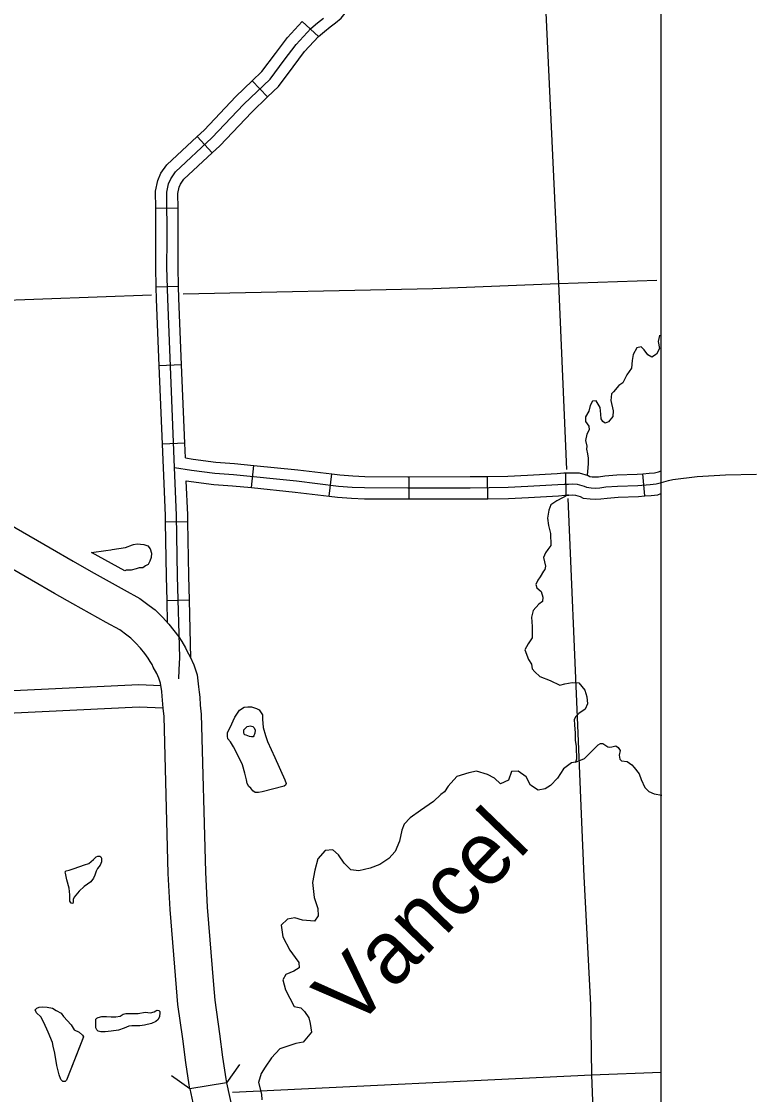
# Model space of a CAD drawing. Extents: x -5566 to 1759129, y -3726 to 731467.
# Drawn here: x -4479.3 to -4442.1, y 243.7 to 298.6 of the extents above; entities that cross this region are included whole.
import ezdxf

# ---------------------------------------------------------------- set-up
doc = ezdxf.new("R2010")
doc.units = 0
doc.layers.add('Default', color=7, linetype='Continuous')
doc.layers.add('R_No Plot', color=7, linetype='Continuous')

msp = doc.modelspace()

# ---------------------------------------------------------------- linework, layer by layer
at = {"layer": 'Default'}
for p, q in [((-4464.085, 297.804), (-4464.921, 298.578)), ((-4466.687, 294.72), (-4467.474, 295.544)), ((-4469.51, 291.865), (-4470.287, 292.698)), ((-4471.258, 289.031), (-4472.397, 289.024)), ((-4471.229, 285.033), (-4472.368, 285.003)), ((-4471.077, 281.034), (-4472.215, 280.989)), ((-4470.916, 277.028), (-4472.054, 276.982)), ((-4467.512, 274.759), (-4467.397, 275.893)), ((-4463.537, 274.323), (-4463.401, 275.454)), ((-4459.465, 274.177), (-4459.465, 275.316)), ((-4455.446, 274.193), (-4455.465, 275.332)), ((-4451.448, 274.371), (-4451.453, 275.51)), ((-4447.431, 274.33), (-4447.528, 275.464)), ((-4470.759, 273.008), (-4471.898, 272.989)), ((-4470.681, 269.005), (-4471.82, 268.974))]:
    msp.add_line(p, q, dxfattribs=at)
for points in [[(-4453.482, 320.514), (-4451.836, 285.18)], [(-4464.085, 297.804), (-4464.083, 297.806), (-4463.78, 298.068), (-4463.49, 298.302), (-4463.213, 298.502), (-4462.932, 298.744), (-4462.543, 299.237), (-4462.261, 299.644), (-4461.9, 300.068), (-4461.596, 300.614), (-4461.455, 301.062)], [(-4471.219, 264.982), (-4471.203, 265.443), (-4471.172, 266.072), (-4471.284, 270.231), (-4471.334, 273.342), (-4471.436, 275.786), (-4471.783, 284.412), (-4471.826, 286.024), (-4471.817, 287.421), (-4471.833, 289.851), (-4471.74, 290.286), (-4471.628, 290.543), (-4471.397, 290.886), (-4469.528, 292.627), (-4467.9, 294.35), (-4466.554, 295.635), (-4465.834, 296.596), (-4465.234, 297.402), (-4464.479, 298.217), (-4464.145, 298.505), (-4463.836, 298.754)], [(-4467.474, 295.544), (-4466.981, 296.015), (-4466.29, 296.937), (-4465.672, 297.767), (-4464.921, 298.578)], [(-4466.687, 294.72), (-4466.126, 295.256), (-4465.377, 296.255), (-4464.795, 297.037), (-4464.085, 297.804)], [(-4470.287, 292.698), (-4469.93, 293.031), (-4468.303, 294.752), (-4467.474, 295.544)], [(-4469.51, 291.865), (-4469.127, 292.222), (-4467.496, 293.948), (-4466.687, 294.72)], [(-4472.397, 289.024), (-4472.403, 289.909), (-4472.285, 290.46), (-4472.13, 290.818), (-4471.833, 291.258), (-4470.287, 292.698)], [(-4471.258, 289.031), (-4471.263, 289.792), (-4471.195, 290.111), (-4471.127, 290.268), (-4470.961, 290.513), (-4469.51, 291.865)], [(-4472.368, 285.003), (-4472.395, 286.018), (-4472.387, 287.421), (-4472.397, 289.024)], [(-4471.229, 285.033), (-4471.256, 286.03), (-4471.247, 287.422), (-4471.258, 289.031)], [(-4470.996, 284.653), (-4458.259, 284.927), (-4451.836, 285.18), (-4446.814, 285.36)], [(-4451.836, 285.18), (-4451.428, 275.683)], [(-4496.493, 283.663), (-4492.047, 283.887), (-4472.622, 284.605)], [(-4472.215, 280.989), (-4472.352, 284.393), (-4472.368, 285.003)], [(-4471.077, 281.034), (-4471.213, 284.431), (-4471.229, 285.033)], [(-4446.675, 282.548), (-4446.674, 282.535), (-4446.755, 282.226)], [(-4446.755, 282.226), (-4446.683, 281.864), (-4446.831, 281.582), (-4447.067, 281.419), (-4447.275, 281.538), (-4447.467, 281.804), (-4447.615, 281.952), (-4447.837, 281.893), (-4448.029, 281.567), (-4448.074, 281.257), (-4448.103, 280.858), (-4448.346, 280.526), (-4448.544, 280.115), (-4448.76, 279.968), (-4449.022, 279.661), (-4449.125, 279.555), (-4449.165, 279.214), (-4449.036, 278.681), (-4449.066, 278.4), (-4449.288, 278.118), (-4449.45, 278.059), (-4449.569, 278.133), (-4449.658, 278.266), (-4449.672, 278.518), (-4449.702, 278.844), (-4449.909, 279.199), (-4450.102, 279.17), (-4450.22, 278.962), (-4450.294, 278.666), (-4450.457, 278.37), (-4450.457, 278.133), (-4450.279, 277.896), (-4450.275, 277.707), (-4450.391, 277.488), (-4450.462, 277.174), (-4450.383, 276.875), (-4450.407, 276.716), (-4450.362, 276.476), (-4450.317, 276.255), (-4450.317, 275.992), (-4450.341, 275.772), (-4450.378, 275.388)], [(-4472.054, 276.982), (-4472.215, 280.989)], [(-4470.916, 277.028), (-4471.077, 281.034)], [(-4494.144, 278.929), (-4493.211, 280.583), (-4483.34, 274.875), (-4477.782, 271.676), (-4476.612, 270.994), (-4475.698, 270.468), (-4474.009, 269.528), (-4473.203, 269.087), (-4472.738, 268.742), (-4472.428, 268.505), (-4472.055, 268.145), (-4471.737, 267.781), (-4471.471, 267.459), (-4471.225, 267.131), (-4471.068, 266.89), (-4470.879, 266.579), (-4470.815, 266.422), (-4470.638, 266.114), (-4470.459, 265.699)], [(-4472.233, 265.028), (-4472.339, 265.263), (-4472.526, 265.588), (-4472.581, 265.723), (-4472.675, 265.879), (-4472.782, 266.043), (-4472.962, 266.284), (-4473.183, 266.55), (-4473.432, 266.835), (-4473.668, 267.063), (-4473.88, 267.225), (-4474.23, 267.485), (-4474.926, 267.866), (-4476.633, 268.816), (-4477.564, 269.351), (-4478.734, 270.033), (-4484.29, 273.232), (-4494.144, 278.929)], [(-4471.898, 272.989), (-4471.904, 273.326), (-4472.005, 275.763), (-4472.054, 276.982)], [(-4470.885, 276.273), (-4470.916, 277.028)], [(-4470.885, 276.273), (-4470.491, 276.208), (-4469.322, 276.056), (-4468.376, 275.992), (-4467.397, 275.893)], [(-4467.397, 275.893), (-4465.145, 275.664), (-4463.401, 275.454)], [(-4471.436, 275.786), (-4470.574, 275.644), (-4469.377, 275.489), (-4468.424, 275.424), (-4465.208, 275.098), (-4463.061, 274.84), (-4462.371, 274.789), (-4461.732, 274.759), (-4459.532, 274.747), (-4456.338, 274.748), (-4454.409, 274.779), (-4453.395, 274.824), (-4451.871, 274.913), (-4451.541, 274.94), (-4451.319, 274.941), (-4451.098, 274.952), (-4450.879, 274.942), (-4450.531, 274.839), (-4450.407, 274.779), (-4450.163, 274.745), (-4449.954, 274.735), (-4449.732, 274.75), (-4449.417, 274.791), (-4448.825, 274.84), (-4447.791, 274.87), (-4447.159, 274.925), (-4446.848, 274.951), (-4446.584, 275.012), (-4446.22, 275.114), (-4446.003, 275.173), (-4444.758, 275.327), (-4443.31, 275.408), (-4441.732, 275.442)], [(-4463.401, 275.454), (-4463.006, 275.407), (-4462.337, 275.358), (-4461.717, 275.328), (-4459.531, 275.316), (-4459.465, 275.316)], [(-4459.465, 275.316), (-4456.343, 275.318), (-4455.465, 275.332)], [(-4455.465, 275.332), (-4454.426, 275.349), (-4453.424, 275.393), (-4451.911, 275.481), (-4451.566, 275.51), (-4451.453, 275.51)], [(-4451.453, 275.51), (-4451.334, 275.511), (-4451.099, 275.522), (-4450.784, 275.508), (-4450.324, 275.372), (-4450.239, 275.331), (-4450.11, 275.313), (-4449.959, 275.305), (-4449.788, 275.317), (-4449.477, 275.357), (-4448.857, 275.409), (-4447.823, 275.439), (-4447.528, 275.464)], [(-4447.528, 275.464), (-4447.208, 275.492), (-4446.936, 275.515), (-4446.725, 275.564), (-4446.6, 275.609), (-4446.6, 275.609), (-4446.6, 275.609), (-4446.6, 275.609)], [(-4470.759, 273.008), (-4470.765, 273.359), (-4470.837, 275.104)], [(-4470.837, 275.104), (-4469.433, 274.922), (-4468.471, 274.857), (-4467.512, 274.759)], [(-4467.512, 274.759), (-4465.271, 274.532), (-4463.537, 274.323)], [(-4463.537, 274.323), (-4463.116, 274.273), (-4462.406, 274.22), (-4461.747, 274.189), (-4459.533, 274.177), (-4459.465, 274.177)], [(-4459.465, 274.177), (-4456.333, 274.179), (-4455.446, 274.193)], [(-4455.446, 274.193), (-4454.392, 274.21), (-4453.366, 274.255), (-4451.83, 274.344), (-4451.516, 274.371), (-4451.448, 274.371)], [(-4451.341, 274.393), (-4451.919, 274.084), (-4452.226, 273.876), (-4452.335, 273.613), (-4452.401, 273.197), (-4452.346, 272.824), (-4452.237, 272.419)], [(-4451.448, 274.371), (-4451.304, 274.372), (-4451.096, 274.382), (-4450.974, 274.376), (-4450.737, 274.306), (-4450.574, 274.227), (-4450.216, 274.178), (-4449.949, 274.164), (-4449.676, 274.183), (-4449.356, 274.224), (-4448.793, 274.271), (-4447.758, 274.301), (-4447.431, 274.33)], [(-4451.365, 274.195), (-4450.868, 262.62), (-4450.669, 257.665), (-4450.539, 254.888), (-4450.203, 248.323), (-4450.151, 244.733)], [(-4447.431, 274.33), (-4447.111, 274.357), (-4446.759, 274.387), (-4446.614, 274.46), (-4446.614, 274.46), (-4446.614, 274.46), (-4446.614, 274.46), (-4446.614, 274.46)], [(-4471.82, 268.974), (-4471.853, 270.218), (-4471.898, 272.989)], [(-4470.681, 269.005), (-4470.714, 270.243), (-4470.759, 273.008)], [(-4452.237, 272.419), (-4452.226, 271.805), (-4452.379, 271.597), (-4452.5, 271.433), (-4452.601, 271.194), (-4452.5, 270.743), (-4452.533, 270.567), (-4452.606, 270.492), (-4452.763, 270.206), (-4452.883, 270.031), (-4452.993, 269.811), (-4452.949, 269.636), (-4452.719, 269.45), (-4452.642, 269.154), (-4452.653, 268.946), (-4452.84, 268.8), (-4453.125, 268.484), (-4453.219, 268.146), (-4453.186, 267.667), (-4453.188, 267.087)], [(-4473.404, 270.615), (-4473.653, 270.542), (-4473.901, 270.542), (-4473.971, 270.512), (-4475.676, 271.441), (-4474.952, 271.545), (-4474.694, 271.578), (-4474.623, 271.599)], [(-4474.623, 271.599), (-4473.944, 271.698), (-4473.59, 271.838), (-4473.527, 271.856), (-4473.348, 271.879), (-4473.005, 271.849), (-4472.801, 271.783), (-4472.68, 271.634), (-4472.616, 271.408), (-4472.629, 271.191), (-4472.695, 270.994), (-4472.792, 270.822), (-4472.925, 270.762), (-4473.064, 270.658), (-4473.246, 270.658), (-4473.404, 270.615)], [(-4471.789, 267.844), (-4471.82, 268.974)], [(-4470.602, 266.051), (-4470.681, 269.005)], [(-4453.188, 267.087), (-4453.389, 266.768), (-4453.552, 266.465)], [(-4453.552, 266.465), (-4453.362, 265.97), (-4453.219, 265.734), (-4453.184, 265.492), (-4453.047, 265.343), (-4452.789, 265.113), (-4452.253, 264.897), (-4451.773, 264.663), (-4451.518, 264.73), (-4451.142, 264.802), (-4450.791, 264.782), (-4450.489, 264.401), (-4450.381, 264.071), (-4450.347, 263.715), (-4450.469, 263.434), (-4450.8, 263.218), (-4450.952, 263.066), (-4451.038, 262.905), (-4451.02, 262.635), (-4450.981, 262.203), (-4450.986, 261.852), (-4450.932, 261.526), (-4450.927, 261.29), (-4450.909, 261.092), (-4450.921, 260.878), (-4450.959, 260.724), (-4451.172, 260.701)], [(-4470.459, 265.699), (-4470.289, 265.19), (-4470.213, 264.581), (-4470.175, 264.31), (-4470.152, 264.048), (-4470.125, 263.643), (-4470.079, 263.187), (-4469.86, 255.114), (-4469.768, 253.326), (-4469.454, 249.352), (-4469.386, 248.563), (-4469.14, 246.84), (-4468.987, 245.647), (-4468.819, 244.545), (-4468.786, 244.346), (-4470.659, 244.032)], [(-4470.659, 244.032), (-4470.694, 244.245), (-4470.867, 245.383), (-4471.022, 246.585), (-4471.273, 248.348), (-4471.346, 249.196), (-4471.663, 253.202), (-4471.758, 255.04), (-4471.975, 263.067), (-4472.017, 263.486), (-4472.045, 263.901), (-4472.062, 264.095), (-4472.095, 264.332), (-4472.15, 264.773), (-4472.233, 265.028)], [(-4472.133, 264.637), (-4473.255, 264.672), (-4481.447, 264.286), (-4482.582, 264.244), (-4483.267, 264.115), (-4483.816, 264.024), (-4484.6, 264.043), (-4485.108, 264.043), (-4486.112, 264.063), (-4486.717, 264.042), (-4490.419, 263.887), (-4490.372, 262.749)], [(-4472.018, 263.493), (-4473.246, 263.532), (-4481.399, 263.148), (-4482.455, 263.109), (-4483.068, 262.994), (-4483.735, 262.882), (-4484.614, 262.904), (-4485.12, 262.904), (-4486.104, 262.924), (-4486.674, 262.904), (-4490.372, 262.749)], [(-4467.975, 260.595), (-4468.188, 261.052), (-4468.421, 261.508), (-4468.573, 261.762), (-4468.715, 261.924), (-4468.736, 262.056), (-4468.736, 262.249), (-4468.604, 262.492), (-4468.361, 263.02), (-4468.117, 263.385), (-4467.884, 263.537), (-4467.691, 263.557), (-4467.509, 263.557), (-4467.255, 263.466), (-4467.113, 263.395), (-4466.941, 263.141), (-4466.941, 262.918), (-4466.911, 262.492), (-4466.789, 262.086), (-4466.688, 261.782)], [(-4467.61, 262.041), (-4467.783, 262.112), (-4467.849, 262.132), (-4467.884, 262.162), (-4467.899, 262.239), (-4467.899, 262.315), (-4467.894, 262.381), (-4467.828, 262.452), (-4467.783, 262.507), (-4467.727, 262.558), (-4467.651, 262.573)], [(-4467.651, 262.573), (-4467.57, 262.583), (-4467.448, 262.543), (-4467.372, 262.482), (-4467.316, 262.37), (-4467.346, 262.208), (-4467.386, 262.066), (-4467.418, 262.026), (-4467.509, 262.026), (-4467.61, 262.041)], [(-4466.688, 261.782), (-4466.312, 260.96), (-4465.805, 259.824), (-4465.745, 259.632), (-4465.775, 259.551), (-4465.846, 259.51), (-4466.961, 259.216), (-4467.154, 259.175), (-4467.326, 259.185), (-4467.438, 259.267), (-4467.549, 259.398), (-4467.651, 259.49), (-4467.732, 259.632), (-4467.772, 259.824), (-4467.843, 260.169), (-4467.975, 260.595)], [(-4450.959, 260.724), (-4450.505, 260.923), (-4449.941, 261.47), (-4449.804, 261.622), (-4449.686, 261.682), (-4449.571, 261.68), (-4449.422, 261.588), (-4449.312, 261.518), (-4449.22, 261.5), (-4449.114, 261.52), (-4448.904, 261.569), (-4448.785, 261.484), (-4448.693, 261.321), (-4448.742, 261.09), (-4448.701, 260.878), (-4448.62, 260.791), (-4448.337, 260.767), (-4448.085, 260.597), (-4447.964, 260.458), (-4447.711, 260.128), (-4447.612, 259.843), (-4447.431, 259.426), (-4447.215, 259.238), (-4446.958, 259.107), (-4446.562, 259.039)], [(-4451.172, 260.701), (-4451.573, 260.383), (-4451.882, 259.914), (-4452.236, 259.534), (-4452.524, 259.367), (-4452.865, 259.297), (-4453.262, 259.562), (-4453.481, 259.985), (-4453.899, 260.268), (-4454.227, 260.258), (-4454.388, 259.815), (-4454.804, 259.626), (-4455.102, 259.91), (-4455.462, 260.103), (-4456.027, 260.271), (-4456.412, 260.187), (-4457.025, 259.995), (-4457.473, 259.504), (-4457.651, 259.213), (-4457.846, 259.073), (-4458.215, 258.718), (-4458.876, 258.265), (-4459.411, 257.886), (-4459.713, 257.566), (-4459.834, 257.262), (-4459.949, 256.684), (-4460.173, 256.169), (-4460.489, 255.81), (-4460.952, 255.503), (-4461.451, 255.318), (-4462.022, 255.174), (-4462.435, 255.221), (-4462.773, 255.57), (-4463.061, 255.99), (-4463.348, 256.257), (-4463.742, 256.222), (-4464.122, 255.79), (-4464.274, 255.203), (-4464.387, 254.587), (-4464.308, 253.821), (-4464.126, 253.243), (-4464.099, 252.878), (-4464.29, 252.601), (-4464.902, 252.661), (-4465.288, 252.771), (-4465.673, 252.713), (-4465.998, 252.399), (-4465.914, 251.801), (-4465.559, 251.125), (-4465.273, 250.743), (-4465.092, 250.485), (-4465.071, 250.227), (-4465.343, 250.053), (-4465.752, 249.872), (-4465.901, 249.6), (-4465.779, 249.095), (-4465.327, 248.242), (-4464.994, 248.179), (-4464.809, 247.99), (-4464.579, 247.659), (-4464.519, 247.372), (-4464.44, 246.937), (-4464.878, 246.428), (-4465.24, 246.345), (-4466.063, 246.08), (-4466.495, 245.616), (-4466.809, 245.142), (-4467.008, 244.815), (-4467.154, 244.36), (-4466.997, 243.762), (-4466.973, 243.469)], [(-4476.565, 255.303), (-4476.03, 255.477), (-4475.809, 255.544), (-4475.569, 255.752), (-4475.435, 255.885), (-4475.355, 255.932), (-4475.248, 255.932), (-4475.201, 255.899), (-4475.174, 255.825), (-4475.174, 255.738), (-4475.174, 255.638), (-4475.234, 255.471), (-4475.375, 255.297), (-4475.442, 255.163), (-4475.515, 254.956), (-4475.575, 254.795), (-4475.716, 254.615)], [(-4475.716, 254.615), (-4476.05, 254.381), (-4476.311, 254.133), (-4476.558, 253.832), (-4476.605, 253.718), (-4476.605, 253.598), (-4476.632, 253.504), (-4476.712, 253.518), (-4476.779, 253.625), (-4476.785, 253.946), (-4476.812, 254.294), (-4476.939, 254.722), (-4477.013, 255.049), (-4477.019, 255.13), (-4476.973, 255.183), (-4476.819, 255.21), (-4476.565, 255.303)], [(-4477.662, 246.404), (-4477.89, 246.936), (-4478.118, 247.427), (-4478.264, 247.72), (-4478.48, 247.924), (-4478.545, 248.065), (-4478.463, 248.153), (-4478.352, 248.211), (-4478.188, 248.223), (-4477.948, 248.211), (-4477.668, 248.164), (-4477.486, 248.047), (-4477.223, 247.895), (-4477.1, 247.726), (-4476.72, 247.31)], [(-4473.763, 247.246), (-4474.014, 247.135), (-4474.295, 247.041), (-4474.669, 246.977), (-4474.973, 246.948), (-4475.201, 246.942), (-4475.336, 246.989), (-4475.412, 247.047), (-4475.464, 247.146), (-4475.464, 247.497), (-4475.453, 247.597), (-4475.412, 247.655), (-4475.33, 247.69), (-4475.149, 247.731), (-4474.903, 247.737), (-4474.675, 247.708), (-4474.429, 247.708), (-4474.219, 247.749), (-4474.061, 247.848), (-4473.921, 247.889)], [(-4473.921, 247.889), (-4473.582, 247.878), (-4473.289, 247.889), (-4472.933, 247.948), (-4472.658, 247.919), (-4472.482, 247.971), (-4472.395, 248.018), (-4472.33, 248.053), (-4472.243, 248.047), (-4472.19, 247.989), (-4472.19, 247.913), (-4472.208, 247.737), (-4472.272, 247.573), (-4472.395, 247.474), (-4472.617, 247.369), (-4472.968, 247.287), (-4473.207, 247.258), (-4473.453, 247.258), (-4473.623, 247.258), (-4473.763, 247.246)], [(-4476.72, 247.31), (-4476.563, 247.059), (-4476.299, 246.924), (-4476.142, 246.772), (-4476.089, 246.696), (-4476.288, 246.158), (-4476.96, 244.473), (-4477.024, 244.403), (-4477.136, 244.403), (-4477.241, 244.52), (-4477.329, 244.76), (-4477.451, 245.234), (-4477.545, 245.854), (-4477.627, 246.211), (-4477.662, 246.404)], [(-4476.089, 246.696), (-4476.96, 244.473)], [(-4468.124, 245.273), (-4468.786, 244.346)], [(-4470.659, 244.033), (-4471.586, 244.694)], [(-4450.151, 244.733), (-4468.479, 243.845)], [(-4446.601, 244.876), (-4450.151, 244.733)], [(-4450.151, 244.733), (-4449.958, 239.914)], [(-4470.659, 244.032), (-4470.301, 242.369), (-4470.088, 241.283), (-4469.993, 240.534)], [(-4468.786, 244.346), (-4468.45, 242.796), (-4468.213, 241.586), (-4468.109, 240.775)]]:
    msp.add_lwpolyline(points, dxfattribs=at)
at = {"layer": 'R_No Plot'}
msp.add_lwpolyline([(-5018.988, 168.239), (-5018.988, 511.979), (-4446.603, 511.979), (-4446.603, 160.504), (-4913.433, 160.504)], dxfattribs=at)

# ---------------------------------------------------------------- texts
at = {"layer": 'Default'}
msp.add_text('Vancel', height=3.2048, rotation=46.0211, dxfattribs=at).set_placement((-4462.284, 246.995))

doc.saveas('drawing.dxf')
